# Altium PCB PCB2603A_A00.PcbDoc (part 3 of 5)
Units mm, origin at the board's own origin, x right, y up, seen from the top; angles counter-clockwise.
Board outline 35.56 x 55.88 mm, 8 copper layers (Top Layer, Signal Layer 1, Signal Layer 2, Signal Layer 3, Signal Layer 4, Signal Layer 5, Signal Layer 6, Bottom Layer), stack 1.497 mm thick; 167 components, 113 nets, 4957 pads, 645 vias.
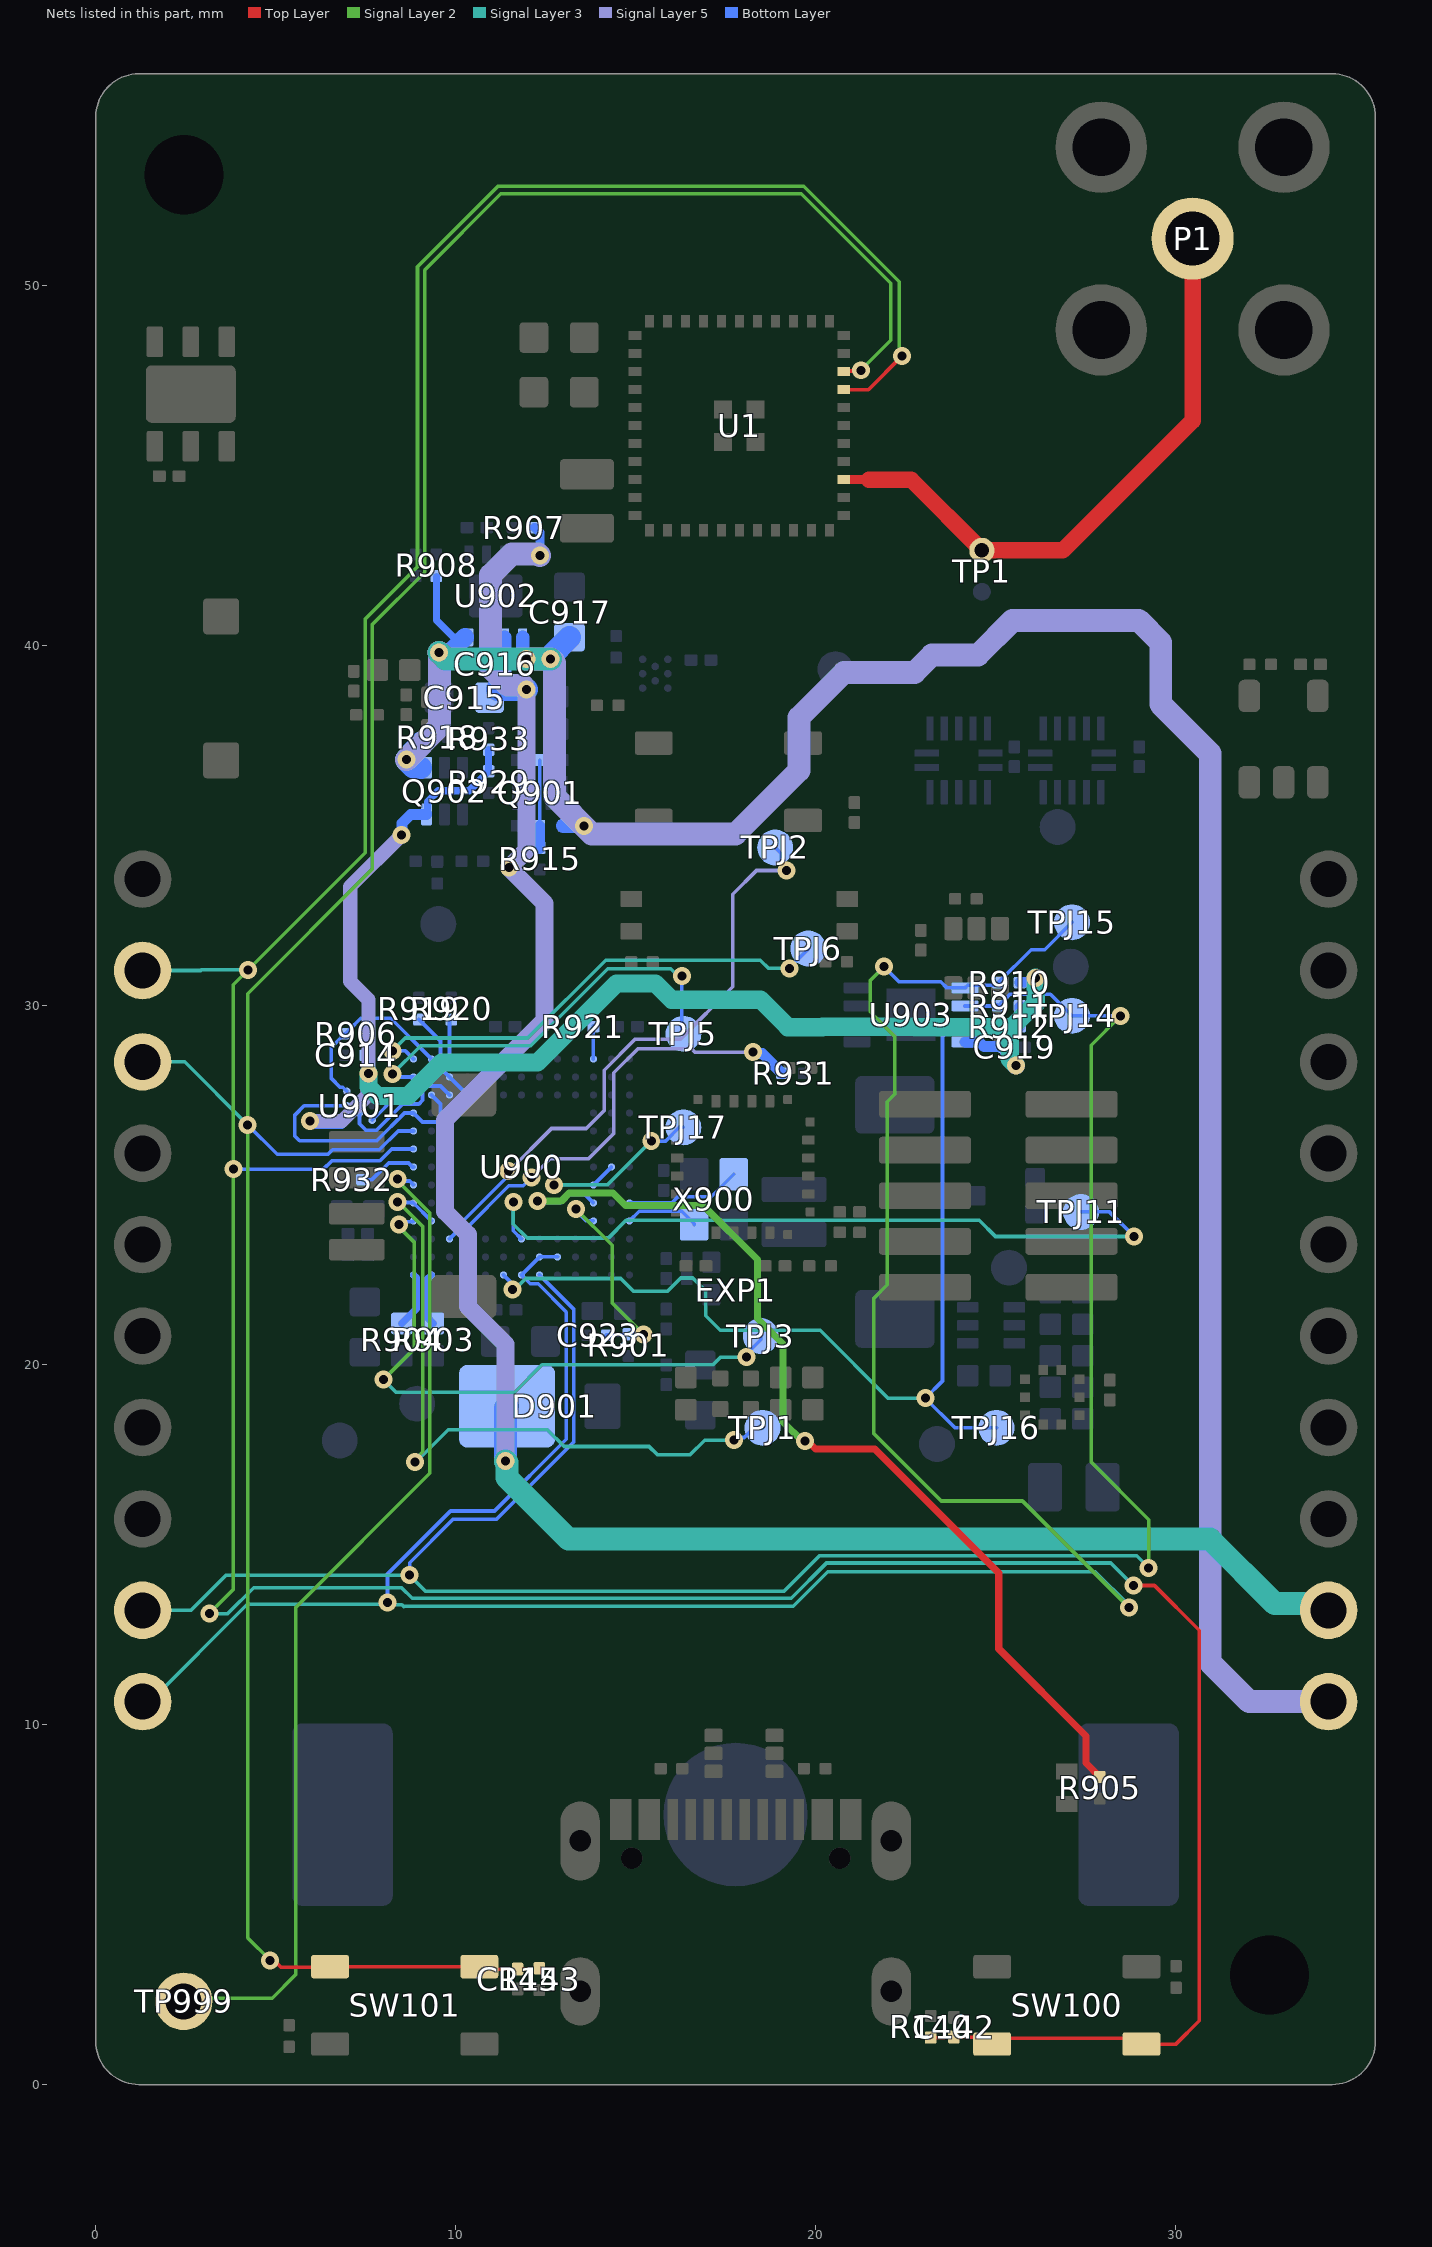
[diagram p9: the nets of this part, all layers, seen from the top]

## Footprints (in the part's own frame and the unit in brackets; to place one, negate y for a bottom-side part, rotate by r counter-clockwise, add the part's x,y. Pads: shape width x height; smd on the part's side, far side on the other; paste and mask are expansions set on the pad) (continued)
LOGO_SEGGER_8.0X4.0_SM [mil] "(210607)" (continued)
  round 0.8 on Mech2: 1(60.2,-56.26) 1(60.2,-56.26) 1(60.36,-56.74) 1(60.36,-56.74) 1(60.44,-56.9) 1(60.44,-56.9) 1(60.44,-56.82) 1(60.52,-29.06) 1(60.52,-29.06) 1(60.6,-57.14) 1(60.6,-57.14) 1(60.68,-57.3) 1(60.68,-57.3) 1(61.16,-36.58) 1(61.16,-36.58) 1(61.16,-29.46) 1(61.32,-57.94) 1(61.32,-57.94) 1(61.48,-29.7) 1(61.48,-29.7) 1(61.56,-58.02) 1(61.56,-58.02) 1(61.72,-58.1) 1(61.72,-58.1) 1(61.8,-36.42) 1(61.8,-36.42) 1(62.2,-58.26) 1(62.2,-58.26) 1(62.28,-40.98) 1(62.28,-40.98) 1(62.28,-36.1) 1(62.28,-36.1) 1(62.28,-30.5) 1(62.28,-30.5) 1(62.44,-58.26) 1(62.44,-58.26) 1(62.6,-35.94) 1(62.6,-35.94) 1(62.68,-58.34) 1(62.68,-58.34) 1(62.68,-35.86) 1(62.68,-30.82) 1(62.68,-30.82) 1(62.84,-41.06) 1(62.84,-41.06) 1(62.84,-31.06) 1(62.92,-58.34) 1(62.92,-58.34) 1(63.08,-35.46) 1(63.08,-35.46) 1(63.24,-58.26) 1(63.24,-58.26) 1(63.4,-34.98) 1(63.4,-34.98) 1(63.4,-32.02) 1(63.4,-32.02) 1(63.48,-34.74) 1(63.48,-34.74) 1(63.56,-58.26) 1(63.56,-58.26) 1(63.56,-32.34) 1(63.56,-32.34) 1(63.64,-41.22) 1(63.64,-41.22) 1(63.64,-34.42) 1(63.64,-34.42) 1(63.72,-34.26) 1(63.72,-34.18) 1(63.72,-34.18) 1(63.72,-32.74) 1(63.72,-32.74) 1(63.72,-32.66) 1(63.88,-58.18) 1(63.88,-58.18) 1(64.04,-41.38) 1(64.04,-41.38) 1(64.12,-58.18) 1(64.12,-58.18) 1(64.28,-41.46) 1(64.28,-41.46) 1(64.36,-58.02) 1(64.36,-58.02) 1(64.52,-57.94) 1(64.52,-57.94) 1(64.6,-41.62) 1(64.6,-41.62) 1(64.76,-57.78) 1(64.76,-57.78) 1(65,-42.02) 1(65,-42.02) 1(65.08,-57.46) 1(65.08,-57.46) 1(65.16,-57.3) 1(65.16,-57.3) 1(65.24,-42.34) 1(65.32,-57.06) 1(65.32,-57.06) 1(65.32,-42.5) 1(65.32,-42.5) 1(65.4,-56.82) 1(65.4,-56.74) 1(65.4,-56.74) 1(65.48,-56.5) 1(65.48,-56.5) 1(65.48,-56.18) 1(65.48,-56.18) 1(65.56,-55.94) 1(65.56,-55.94) 1(65.56,-55.14) 1(65.56,-53.54) 1(65.56,-51.94) 1(65.56,-50.34) 1(65.56,-48.74) 1(65.56,-47.14) 1(65.56,-45.54) 1(65.56,-43.94) 1(65.56,-43.46) 1(65.56,-43.46) 1(72.68,-54.02) 1(72.68,-54.02) 1(72.68,-52.66) 1(72.68,-51.06) 1(72.68,-49.46) 1(72.68,-47.86) 1(72.68,-46.26) 1(72.68,-44.66) 1(72.68,-43.06) 1(72.68,-41.46) 1(72.68,-39.86) 1(72.68,-38.18) 1(72.68,-36.58) 1(72.68,-34.98) 1(72.68,-33.38) 1(72.68,-31.78) 1(72.68,-30.5) 1(72.68,-30.5) 1(72.76,-54.58) 1(72.76,-54.58) 1(72.76,-54.26) 1(72.76,-30.18) 1(72.76,-29.94) 1(72.76,-29.94) 1(72.92,-55.3) 1(72.92,-55.3) 1(72.92,-55.06) 1(72.92,-55.06) 1(72.92,-29.38) 1(72.92,-29.38) 1(72.92,-29.14) 1(72.92,-29.14) 1(73,-55.54) 1(73,-55.54) 1(73,-28.98) 1(73,-28.98) 1(73.16,-55.78) 1(73.16,-55.78) 1(73.16,-28.74) 1(73.16,-28.74) 1(73.24,-55.94) 1(73.24,-28.58) 1(73.4,-56.26) 1(73.4,-56.26) 1(73.4,-28.26) 1(73.4,-28.26) 1(73.56,-56.42) 1(73.56,-56.42) 1(73.56,-28.1) 1(73.56,-28.1) 1(73.64,-56.58) 1(73.64,-56.58) 1(73.64,-27.94) 1(73.64,-27.94) 1(73.72,-56.66) 1(73.72,-56.66) 1(73.88,-56.74) 1(73.88,-56.74) 1(73.88,-27.7) 1(73.88,-27.7) 1(74.04,-56.9) 1(74.04,-56.9) 1(74.04,-27.62) 1(74.04,-27.62) 1(74.2,-27.46) 1(74.2,-27.46) 1(74.36,-57.06) 1(74.36,-57.06) 1(74.36,-27.46) 1(74.36,-27.46) 1(74.6,-57.14) 1(74.6,-57.14) 1(74.6,-27.3) 1(74.6,-27.3) 1(74.76,-57.22) 1(74.76,-57.22) 1(74.76,-27.22) 1(74.76,-27.22) 1(75,-57.3) 1(75,-57.3) 1(75,-27.22) 1(75,-27.22) 1(75.48,-27.06) 1(75.48,-27.06) 1(75.96,-57.46) 1(75.96,-57.46) 1(75.96,-26.98) 1(75.96,-26.98) 1(75.96,-26.98) 1(76.52,-57.54) 1(76.52,-57.54) 1(76.52,-26.98) 1(76.52,-26.98) 1(77.16,-26.9) 1(77.16,-26.9) 1(79.96,-51.94) 1(79.96,-51.94) 1(79.96,-51.06) 1(79.96,-49.46) 1(79.96,-47.86) 1(79.96,-46.26) 1(79.96,-44.66) 1(79.96,-44.02) 1(79.96,-44.02) 1(79.96,-38.74) 1(79.96,-38.74) 1(79.96,-38.18) 1(79.96,-36.58) 1(79.96,-34.98) 1(79.96,-33.38) 1(79.96,-32.26) 1(79.96,-32.26) 1(93.72,-38.74) 1(93.72,-38.74) 1(94.2,-44.02) 1(94.2,-44.02) 1(94.2,-38.82) 1(94.2,-38.82) 1(94.68,-43.94) 1(94.68,-43.94) 1(94.68,-38.82) 1(94.68,-38.82) 1(95.08,-43.94) 1(95.08,-43.94) 1(95.08,-38.9) 1(95.08,-38.9) 1(95.24,-26.9) 1(95.24,-26.9) 1(95.48,-43.86) 1(95.48,-43.86) 1(95.48,-38.9) 1(95.48,-38.9) 1(95.72,-32.26) 1(95.72,-32.26) 1(95.72,-26.98) 1(95.72,-26.98) 1(95.8,-43.78) 1(95.8,-43.78) 1(95.8,-39.06) 1(95.8,-39.06) 1(96.12,-43.62) 1(96.12,-43.62) 1(96.12,-39.14) 1(96.12,-39.14) 1(96.2,-32.18) 1(96.2,-32.18) 1(96.2,-26.98) 1(96.2,-26.98) 1(96.28,-26.98) 1(96.44,-43.54) 1(96.44,-43.54) 1(96.44,-39.3) 1(96.44,-39.3) 1(96.6,-32.18) 1(96.6,-32.18) 1(96.68,-51.94) 1(96.68,-51.94) 1(96.92,-43.22) 1(96.92,-43.22) 1(97.08,-43.06) 1(97.08,-42.98) 1(97.08,-42.98) 1(97.16,-57.54) 1(97.16,-57.54) 1(97.16,-52.02) 1(97.16,-52.02) 1(97.16,-39.78) 1(97.16,-39.78) 1(97.24,-39.86) 1(97.4,-32.02) 1(97.4,-32.02) 1(97.4,-27.22) 1(97.4,-27.22) 1(97.48,-42.58) 1(97.48,-42.58) 1(97.48,-40.26) 1(97.48,-40.26) 1(97.56,-52.02) 1(97.56,-52.02) 1(97.56,-42.26) 1(97.56,-42.26) 1(97.56,-40.5) 1(97.56,-40.5) 1(97.64,-42.02) 1(97.64,-42.02) 1(97.72,-41.7) 1(97.72,-41.7) 1(97.72,-41.46) 1(97.72,-41.14) 1(97.72,-41.14) 1(97.72,-31.86) 1(97.72,-31.86) 1(97.72,-27.3) 1(97.72,-27.3) 1(97.96,-31.78) 1(98.04,-31.78) 1(98.04,-31.78) 1(98.04,-27.46) 1(98.04,-27.46) 1(98.28,-31.62) 1(98.28,-31.62) 1(98.36,-57.3) 1(98.36,-57.3) 1(98.36,-52.18) 1(98.36,-52.18) 1(98.52,-31.38) 1(98.52,-31.38) 1(98.52,-27.78) 1(98.52,-27.78) 1(98.68,-57.14) 1(98.68,-57.14) 1(98.76,-31.22) 1(98.76,-31.22) 1(98.76,-28.02) 1(98.76,-28.02) 1(98.92,-56.98) 1(98.92,-56.98) 1(98.92,-30.98) 1(98.92,-30.98) 1(98.92,-28.26) 1(98.92,-28.26) 1(99,-52.5) 1(99,-52.5) 1(99,-30.74) 1(99,-30.74) 1(99,-28.5) 1(99,-28.5) 1(99.08,-28.58) 1(99.16,-30.5) 1(99.16,-30.5) 1(99.16,-28.74) 1(99.16,-28.74) 1(99.24,-56.82) 1(99.24,-56.82) 1(99.24,-30.26) 1(99.24,-30.26) 1(99.24,-28.98) 1(99.24,-28.98) 1(99.32,-52.66) 1(99.32,-30.18) 1(99.32,-29.94) 1(99.32,-29.94) 1(99.32,-29.3) 1(99.32,-29.3) 1(99.48,-56.66) 1(99.48,-56.66) 1(99.48,-52.82) 1(99.48,-52.82) 1(99.64,-56.42) 1(99.64,-56.42) 1(99.72,-53.06) 1(99.72,-53.06) 1(99.88,-56.18) 1(99.88,-56.18) 1(99.88,-53.3) 1(99.88,-53.3) 1(99.96,-55.94) 1(99.96,-55.94) 1(99.96,-55.94) 1(100.12,-55.7) 1(100.12,-55.7) 1(100.12,-53.78) 1(100.12,-53.78) 1(100.2,-55.38) 1(100.2,-55.38) 1(100.2,-55.06) 1(100.2,-55.06) 1(100.2,-54.42) 1(100.2,-54.42) 1(100.2,-54.26) 1(100.2,-54.1) 1(100.2,-54.1) 1(100.28,-54.74) 1(100.28,-54.74) 1(105.4,-54.98) 1(105.4,-54.98) 1(105.4,-54.66) 1(105.4,-53.06) 1(105.4,-51.46) 1(105.4,-49.86) 1(105.4,-48.26) 1(105.4,-46.66) 1(105.4,-45.06) 1(105.4,-43.46) 1(105.4,-41.86) 1(105.4,-40.26) 1(105.4,-38.58) 1(105.4,-36.98) 1(105.4,-35.38) 1(105.4,-33.78) 1(105.4,-32.18) 1(105.4,-31.06) 1(105.4,-31.06) 1(105.48,-55.38) 1(105.48,-55.38) 1(105.48,-30.58) 1(105.64,-56.02) 1(105.64,-56.02) 1(105.64,-29.38) 1(105.64,-29.38) 1(105.72,-29.14) 1(105.72,-29.14) 1(105.8,-56.34) 1(105.8,-56.34) 1(105.8,-56.34) 1(105.8,-28.98) 1(105.8,-28.98) 1(105.8,-28.98) 1(105.88,-28.74) 1(105.88,-28.74) 1(106.04,-28.42) 1(106.04,-28.42) 1(106.12,-56.82) 1(106.12,-56.82) 1(106.2,-28.26) 1(106.2,-28.26) 1(106.36,-27.94) 1(106.36,-27.94) 1(106.52,-27.86) 1(106.52,-27.86) 1(106.6,-57.3) 1(106.6,-57.3) 1(106.68,-27.7) 1(106.68,-27.7) 1(106.84,-57.46) 1(106.84,-57.46) 1(106.84,-27.62) 1(106.84,-27.62) 1(107,-27.46) 1(107,-27.46) 1(107.16,-57.62) 1(107.16,-57.62) 1(107.16,-27.46) 1(107.16,-27.46) 1(107.24,-27.38) 1(107.32,-27.3) 1(107.32,-27.3) 1(107.48,-57.7) 1(107.48,-57.7) 1(107.56,-27.22) 1(107.56,-27.22) 1(107.8,-27.22) 1(107.8,-27.22) 1(108.2,-27.06) 1(108.2,-27.06) 1(108.68,-57.94) 1(108.68,-57.94) 1(108.76,-26.98) 1(108.76,-26.98) 1(109.32,-26.98) 1(109.32,-26.98) 1(109.56,-57.94) 1(109.56,-57.94) 1(109.96,-26.9) 1(109.96,-26.9) 1(110.04,-57.86) 1(110.04,-57.86) 1(110.44,-57.78) 1(110.44,-57.78) 1(111.08,-57.62) 1(111.08,-57.62) 1(111.4,-57.46) 1(111.4,-57.46) 1(111.64,-57.3) 1(111.64,-57.3) 1(111.96,-57.06) 1(111.96,-57.06) 1(112.12,-56.9) 1(112.12,-56.9) 1(112.36,-56.58) 1(112.36,-56.58) 1(112.44,-56.34) 1(112.44,-56.34) 1(112.44,-56.34) 1(112.6,-56.02) 1(112.6,-56.02) 1(112.76,-55.38) 1(112.76,-55.38) 1(112.84,-54.98) 1(112.84,-54.98) 1(112.84,-54.66) 1(112.84,-53.06) 1(112.84,-51.46) 1(112.84,-49.86) 1(112.84,-48.26) 1(112.84,-46.66) 1(112.84,-45.62) 1(112.84,-45.62) 1(112.84,-40.34) 1(112.84,-40.34) 1(112.84,-40.26) 1(112.84,-38.58) 1(112.84,-36.98) 1(112.84,-35.38) 1(112.84,-33.78) 1(112.84,-32.18) 1(112.84,-32.18) 1(112.84,-32.18) 1(120.68,-45.62) 1(120.68,-45.62) 1(121.4,-45.7) 1(121.4,-45.7) 1(121.88,-32.18) 1(121.88,-32.18) 1(122.04,-45.7) 1(122.04,-45.7) 1(122.2,-32.18) 1(122.28,-40.34) 1(122.28,-40.34) 1(122.52,-32.26) 1(122.52,-32.26) 1(122.92,-40.26) 1(122.92,-40.26) 1(122.92,-26.9) 1(122.92,-26.9) 1(123,-40.26) 1(123.16,-45.86) 1(123.16,-45.86) 1(123.16,-32.26) 1(123.16,-32.26) 1(123.56,-45.94) 1(123.56,-45.94) 1(123.64,-32.34) 1(123.64,-32.34) 1(123.64,-26.98) 1(123.64,-26.98) 1(124.04,-46.1) 1(124.04,-46.1) 1(124.04,-40.1) 1(124.04,-40.1) 1(124.2,-46.18) 1(124.2,-46.18) 1(124.2,-32.5) 1(124.2,-32.5) 1(124.36,-46.34) 1(124.36,-46.34) 1(124.36,-26.98) 1(124.36,-26.98) 1(124.6,-32.58) 1(124.6,-32.58) 1(124.68,-46.5) 1(124.68,-46.5) 1(124.92,-46.66) 1(125,-39.78) 1(125,-39.78) 1(125,-32.82) 1(125,-32.82) 1(125,-27.06) 1(125,-27.06) 1(125.08,-46.9) 1(125.08,-46.9) 1(125.16,-47.14) 1(125.16,-47.14) 1(125.16,-39.7) 1(125.16,-39.7) 1(125.24,-32.9) 1(125.24,-32.9) 1(125.32,-47.3) 1(125.32,-47.3) 1(125.4,-39.54) 1(125.4,-39.54) 1(125.4,-32.98) 1(125.4,-32.98) 1(125.48,-47.78) 1(125.48,-47.78) 1(125.56,-48.1) 1(125.56,-48.1) 1(125.64,-48.26) 1(125.64,-33.14) 1(125.64,-33.14) 1(125.64,-27.06) 1(125.64,-27.06) 1(125.72,-48.66) 1(125.72,-48.66) 1(125.72,-39.38) 1(125.72,-39.38) 1(125.8,-33.22) 1(125.8,-33.22) 1(125.88,-49.38) 1(125.88,-49.38) 1(125.96,-33.38) 1(125.96,-33.38) 1(126.04,-51.06) 1(126.04,-51.06) 1(126.04,-50.18) 1(126.04,-50.18) 1(126.04,-49.86) 1(126.04,-33.54) 1(126.04,-33.54) 1(126.12,-51.46) 1(126.2,-52.18) 1(126.2,-52.18) 1(126.2,-33.62) 1(126.2,-33.62) 1(126.28,-53.14) 1(126.28,-53.14) 1(126.28,-53.06) 1(126.36,-33.78) 1(126.36,-33.78) 1(126.44,-54.02) 1(126.44,-54.02) 1(126.44,-38.66) 1(126.44,-38.66) 1(126.44,-38.58) 1(126.44,-34.02) 1(126.44,-34.02) 1(126.44,-33.78) 1(126.6,-54.82) 1(126.6,-54.82) 1(126.6,-54.66) 1(126.6,-38.42) 1(126.6,-38.42) 1(126.6,-34.18) 1(126.6,-34.18) 1(126.76,-34.5) 1(126.76,-34.5) 1(126.84,-55.78) 1(126.84,-55.78) 1(126.84,-37.94) 1(126.84,-37.94) 1(126.84,-34.74) 1(126.84,-34.74) 1(126.92,-37.7) 1(126.92,-37.7) 1(126.92,-37.46) 1(126.92,-37.46) 1(126.92,-34.9) 1(126.92,-34.9) 1(126.92,-27.22) 1(126.92,-27.22) 1(127,-56.02) 1(127,-56.02) 1(127,-37.22) 1(127,-37.22) 1(127,-35.3) 1(127,-35.3) 1(127,-35.14) 1(127,-35.14) 1(127.08,-56.26) 1(127.08,-56.26) 1(127.08,-36.98) 1(127.08,-36.74) 1(127.08,-36.74) 1(127.08,-35.78) 1(127.08,-35.78) 1(127.08,-35.38) 1(127.16,-56.34) 1(127.24,-56.5) 1(127.24,-56.5) 1(127.32,-56.66) 1(127.32,-56.66) 1(127.48,-56.82) 1(127.48,-56.82) 1(127.48,-27.38) 1(127.48,-27.38) 1(127.56,-56.98) 1(127.56,-56.98) 1(127.56,-27.38) 1(127.72,-57.06) 1(127.72,-57.06) 1(127.88,-57.22) 1(127.88,-57.22) 1(128.04,-57.3) 1(128.04,-57.3) 1(128.04,-27.46) 1(128.04,-27.46) 1(128.2,-57.46) 1(128.2,-57.46) 1(128.36,-57.54) 1(128.36,-57.54) 1(128.6,-57.62) 1(128.6,-57.62) 1(128.6,-27.62) 1(128.6,-27.62) 1(128.76,-57.7) 1(128.76,-57.7) 1(129.16,-42.82) 1(129.16,-42.82) 1(129.56,-27.94) 1(129.56,-27.94) 1(129.64,-43.06) 1(129.64,-43.06) 1(130.04,-28.18) 1(130.04,-28.18) 1(130.12,-43.22) 1(130.12,-43.22) 1(130.12,-42.58) 1(130.12,-42.58) 1(130.2,-57.94) 1(130.2,-57.94) 1(130.36,-42.42) 1(130.36,-42.42) 1(130.52,-43.38) 1(130.52,-43.38) 1(130.52,-28.34) 1(130.52,-28.34) 1(130.68,-43.46) 1(130.68,-42.34) 1(130.68,-42.34) 1(131.32,-43.86) 1(131.32,-43.86) 1(131.32,-28.82) 1(131.32,-28.82) 1(131.4,-41.86) 1(131.4,-41.86) 1(131.4,-41.86) 1(131.56,-57.94) 1(131.56,-57.94) 1(131.56,-28.98) 1(131.64,-44.1) 1(131.64,-44.1) 1(131.64,-29.06) 1(131.64,-29.06) 1(131.72,-41.7) 1(131.72,-41.7) 1(131.96,-57.86) 1(131.96,-57.86) 1(131.96,-41.54) 1(131.96,-41.54) 1(132.04,-29.38) 1(132.04,-29.38) 1(132.28,-57.78) 1(132.28,-57.78) 1(132.36,-41.14) 1(132.36,-41.14) 1(132.36,-29.62) 1(132.36,-29.62) 1(132.52,-44.98) 1(132.52,-44.98) 1(132.6,-57.62) 1(132.6,-57.62) 1(132.6,-45.06) 1(132.6,-40.98) 1(132.6,-40.98) 1(132.6,-29.94) 1(132.6,-29.94) 1(132.68,-45.38) 1(132.68,-45.38) 1(132.92,-57.54) 1(132.92,-57.54) 1(132.92,-45.7) 1(132.92,-45.7) 1(132.92,-40.5) 1(132.92,-40.5) 1(132.92,-30.34) 1(132.92,-30.34) 1(133.08,-46.1) 1(133.08,-46.1) 1(133.16,-57.38) 1(133.16,-57.38) 1(133.16,-40.34) 1(133.16,-40.34) 1(133.16,-30.58) 1(133.24,-46.58) 1(133.24,-46.58) 1(133.24,-40.26) 1(133.32,-46.66) 1(133.32,-40.1) 1(133.32,-40.1) 1(133.4,-30.98) 1(133.4,-30.98) 1(133.48,-57.22) 1(133.48,-57.22) 1(133.48,-39.78) 1(133.48,-39.78) 1(133.56,-48.26) 1(133.64,-50.82) 1(133.64,-50.82) 1(133.64,-49.86) 1(133.64,-48.98) 1(133.64,-48.98) 1(133.64,-39.54) 1(133.64,-39.54) 1(133.64,-31.38) 1(133.64,-31.38) 1(133.72,-56.98) 1(133.72,-56.98) 1(133.72,-51.38) 1(133.72,-51.38) 1(133.72,-39.3) 1(133.72,-39.3) 1(133.8,-52.1) 1(133.8,-52.1) 1(133.8,-51.78) 1(133.8,-51.78) 1(133.8,-51.46) 1(133.88,-56.74) 1(133.88,-56.74) 1(133.88,-39.06) 1(133.88,-39.06) 1(133.96,-52.74) 1(133.96,-52.74) 1(133.96,-38.74) 1(133.96,-38.74) 1(133.96,-32.18) 1(133.96,-32.18) 1(133.96,-32.18) 1(134.04,-56.58) 1(134.04,-56.58) 1(134.04,-53.22) 1(134.04,-53.22) 1(134.04,-53.06) 1(134.04,-38.58) 1(134.04,-38.5) 1(134.04,-38.5) 1(134.12,-32.66) 1(134.12,-32.66) 1(134.2,-56.34) 1(134.2,-56.26) 1(134.2,-56.26) 1(134.2,-53.7) 1(134.2,-53.7) 1(134.2,-38.18) 1(134.2,-38.18) 1(134.2,-37.94) 1(134.2,-37.94) 1(134.2,-33.06) 1(134.2,-33.06) 1(134.28,-54.18) 1(134.28,-54.18) 1(134.36,-56.02) 1(134.36,-56.02) 1(134.36,-33.54) 1(134.36,-33.54) 1(134.44,-55.78) 1(134.44,-55.78) 1(134.44,-54.66) 1(134.44,-54.58) 1(134.44,-54.58) 1(134.44,-36.98) 1(134.44,-36.98) 1(134.44,-36.98) 1(134.44,-34.58) 1(134.44,-34.58) 1(134.44,-34.02) 1(134.44,-34.02) 1(134.44,-33.78) 1(134.52,-36.34) 1(134.52,-36.34) 1(134.52,-35.38) 1(134.52,-35.06) 1(134.52,-35.06) 1(135.4,-5.14) 1(135.4,-5.14) 1(135.4,14.54) 1(135.4,14.54) 1(135.8,-14.34) 1(135.8,-14.34) 1(135.8,-5.22) 1(135.8,-5.22) 1(135.8,5.34) 1(135.8,5.34) 1(135.8,14.46) 1(135.8,14.46) 1(136.2,-5.22) 1(136.2,-5.22) 1(136.2,14.46) 1(136.2,14.46) 1(137,-14.1) 1(137,-14.1) 1(137,-5.38) 1(137,-5.38) 1(137,5.58) 1(137,5.58) 1(137,14.3) 1(137,14.3) 1(137.16,-14.02) 1(137.64,-13.78) 1(137.64,-13.78) 1(137.64,-5.7) 1(137.64,-5.7) 1(137.64,13.98) 1(137.64,13.98) 1(137.8,-13.62) 1(137.8,-13.62) 1(137.8,-5.86) 1(137.8,-5.86) 1(137.8,5.98) 1(137.8,5.98) 1(137.96,-13.54) 1(137.96,-13.54) 1(137.96,-5.94) 1(137.96,-5.94) 1(137.96,13.66) 1(137.96,13.66) 1(138.04,-5.94) 1(138.12,13.58) 1(138.12,13.58) 1(138.28,-13.22) 1(138.28,-13.22) 1(138.28,-6.26) 1(138.28,-6.26) 1(138.28,6.46) 1(138.28,6.46) 1(138.28,13.42) 1(138.28,13.42) 1(138.36,-13.06) 1(138.36,-13.06) 1(138.36,-6.42) 1(138.36,-6.42) 1(138.36,6.62) 1(138.36,6.62) 1(138.36,13.18) 1(138.36,13.18) 1(138.36,13.42) 1(138.52,-12.82) 1(138.52,-12.82) 1(138.52,-6.66) 1(138.52,-6.66) 1(138.52,6.78) 1(138.52,6.78) 1(138.52,13.02) 1(138.52,13.02) 1(138.6,-12.66) 1(138.6,-12.66) 1(138.6,6.94) 1(138.68,-12.42) 1(138.76,-12.18) 1(138.76,-12.18) 1(138.76,-7.38) 1(138.76,-7.38) 1(138.76,7.5) 1(138.76,7.5) 1(138.76,12.3) 1(138.76,12.3) 1(138.92,-11.86) 1(138.92,-11.86) 1(138.92,-11.62) 1(138.92,-11.62) 1(138.92,-7.94) 1(138.92,-7.94) 1(138.92,-7.62) 1(138.92,-7.62) 1(138.92,-7.62) 1(138.92,7.82) 1(138.92,7.82) 1(138.92,8.06) 1(138.92,8.06) 1(138.92,11.74) 1(138.92,11.74) 1(138.92,11.82) 1(138.92,12.06) 1(138.92,12.06) 1(139,-11.3) 1(139,-11.3) 1(139,8.38) 1(139,8.38) 1(139.08,-10.9) 1(139.08,-10.9) 1(139.08,-10.82) 1(139.08,-9.22) 1(139.08,-8.58) 1(139.08,-8.58) 1(139.08,8.62) 1(139.08,8.78) 1(139.08,8.78) 1(139.08,10.22) 1(139.08,11.1) 1(139.08,11.1) 1(145,78.78) 1(145,78.78) 1(145.32,72.22) 1(145.32,72.22) 1(145.56,-72.02) 1(145.56,-72.02) 1(145.56,72.14) 1(145.56,72.14) 1(145.64,-78.58) 1(145.64,-78.58) 1(145.64,78.7) 1(145.64,78.7) 1(145.88,-71.94) 1(145.88,-71.94) 1(145.88,72.14) 1(145.88,72.14) 1(146.12,-71.94) 1(146.12,-71.94) 1(146.12,72.06) 1(146.12,72.06) 1(146.28,78.7) 1(146.28,78.7) 1(146.44,-71.86) 1(146.44,-71.86) 1(146.44,71.98) 1(146.44,71.98) 1(146.68,-71.78) 1(146.68,-71.78) 1(146.68,71.9) 1(146.68,71.9) 1(146.92,78.62) 1(146.92,78.62) 1(147,-71.62) 1(147,-71.62) 1(147,71.82) 1(147,71.82) 1(147.24,-71.54) 1(147.24,-71.54) 1(147.24,71.74) 1(147.24,71.74) 1(147.48,-71.38) 1(147.48,-71.38) 1(147.56,-78.34) 1(147.56,-78.34) 1(147.56,78.46) 1(147.56,78.46) 1(147.72,-71.3) 1(147.72,-71.3) 1(147.72,71.42) 1(147.72,71.42) 1(147.96,71.34) 1(147.96,71.34) 1(148.12,-78.18) 1(148.12,-78.18) 1(148.12,78.3) 1(148.12,78.3) 1(148.2,71.18) 1(148.2,71.18) 1(148.44,-70.82) 1(148.44,-70.82) 1(148.44,70.94) 1(148.44,70.94) 1(148.44,71.02) 1(148.68,70.78) 1(148.68,70.78) 1(148.76,-78.02) 1(148.76,-78.02) 1(148.76,-70.5) 1(148.76,78.14) 1(148.76,78.14) 1(149.32,-69.94) 1(149.32,-69.94) 1(149.32,70.14) 1(149.32,70.14) 1(149.32,77.98) 1(149.32,77.98) 1(149.48,-69.7) 1(149.48,-69.7) 1(149.48,69.9) 1(149.48,69.9) 1(149.72,-69.46) 1(149.72,-69.46) 1(149.72,69.66) 1(149.72,69.66) 1(149.88,69.42) 1(149.88,69.42) 1(149.88,77.74) 1(149.88,77.74) 1(149.96,69.42) 1(150.04,-68.98) 1(150.04,-68.98) 1(150.04,69.1) 1(150.04,69.1) 1(150.12,-68.9) 1(150.2,-68.66) 1(150.2,-68.66) 1(150.2,68.86) 1(150.2,68.86) 1(150.28,-68.42) 1(150.28,-68.42) 1(150.28,68.54) 1(150.28,68.54) 1(150.44,-77.3) 1(150.44,-77.3) 1(150.44,-68.1) 1(150.44,-68.1) 1(150.44,68.3) 1(150.44,68.3) 1(150.44,77.42) 1(150.44,77.42) 1(150.52,77.42) 1(150.6,-67.46) 1(150.6,-67.46) 1(150.6,67.74) 1(150.68,-67.3) 1(150.68,-67.22) 1(150.68,-67.22) 1(150.76,-66.82) 1(150.76,-66.82) 1(150.84,-66.5) 1(150.84,-66.5) 1(150.84,-66.18) 1(150.84,-66.18) 1(150.84,66.38) 1(150.84,66.38) 1(150.84,66.7) 1(150.84,66.7) 1(150.92,-65.86) 1(150.92,-65.86) 1(150.92,-65.7) 1(150.92,-64.1) 1(150.92,-62.5) 1(150.92,-60.9) 1(150.92,-59.22) 1(150.92,-57.62) 1(150.92,-56.02) 1(150.92,-54.42) 1(150.92,-52.82) 1(150.92,-51.22) 1(150.92,-49.62) 1(150.92,-48.02) 1(150.92,-46.42) 1(150.92,-44.82) 1(150.92,-43.14) 1(150.92,-41.54) 1(150.92,-39.94) 1(150.92,-38.34) 1(150.92,-36.74) 1(150.92,-35.14) 1(150.92,-33.54) 1(150.92,-31.94) 1(150.92,-30.34) 1(150.92,-28.74) 1(150.92,-27.06) 1(150.92,-25.46) 1(150.92,-23.86) 1(150.92,-22.26) 1(150.92,-20.66) 1(150.92,-19.06) 1(150.92,-17.46) 1(150.92,-15.86) 1(150.92,-14.26) 1(150.92,-12.66) 1(150.92,-10.98) 1(150.92,-9.38) 1(150.92,-7.78) 1(150.92,-6.18) 1(150.92,-4.58) 1(150.92,-2.98) 1(150.92,-1.38) 1(150.92,0.22) 1(150.92,1.82) 1(150.92,3.42) 1(150.92,5.1) 1(150.92,6.7) 1(150.92,8.3) 1(150.92,9.9) 1(150.92,11.5) 1(150.92,13.1) 1(150.92,14.7) 1(150.92,16.3) 1(150.92,17.9) 1(150.92,19.5) 1(150.92,21.18) 1(150.92,22.78) 1(150.92,24.38) 1(150.92,25.98) 1(150.92,27.58) 1(150.92,29.18) 1(150.92,30.78) 1(150.92,32.38) 1(150.92,33.98) 1(150.92,35.58) 1(150.92,37.26) 1(150.92,38.86) 1(150.92,40.46) 1(150.92,42.06) 1(150.92,43.66) 1(150.92,45.26) 1(150.92,46.86) 1(150.92,48.46) 1(150.92,50.06) 1(150.92,51.66) 1(150.92,53.34) 1(150.92,54.94) 1(150.92,56.54) 1(150.92,58.14) 1(150.92,59.74) 1(150.92,61.34) 1(150.92,62.94) 1(150.92,64.54) 1(150.92,66.06) 1(150.92,66.06) 1(150.92,66.14) 1(151,-76.98) 1(151,-76.98) 1(151,77.18) 1(151,77.18) 1(151.08,-76.98) 1(151.48,-76.66) 1(151.48,-76.66) 1(151.48,76.86) 1(151.48,76.86) 1(152.04,-76.34) 1(152.04,-76.34) 1(152.04,76.46) 1(152.04,76.46) 1(152.52,76.06) 1(152.52,76.06) 1(152.92,75.82) 1(153,75.74) 1(153,75.74) 1(153.24,-75.3) 1(153.48,-75.14) 1(153.48,-75.14) 1(153.88,74.86) 1(153.88,74.86) 1(154.28,-74.18) 1(154.28,-74.18) 1(154.44,74.22) 1(154.68,-73.78) 1(154.68,-73.78) 1(154.68,73.9) 1(154.68,73.9) 1(154.76,-73.7) 1(155,-73.22) 1(155,-73.22) 1(155.32,-72.74) 1(155.32,-72.74) 1(155.32,72.94) 1(155.32,72.94) 1(155.64,72.62) 1(155.72,-72.18) 1(155.72,-72.18) 1(155.72,72.38) 1(155.72,72.38) 1(155.8,-72.1) 1(155.96,-71.7) 1(155.96,-71.7) 1(155.96,71.82) 1(155.96,71.82) 1(156.28,-71.14) 1(156.28,-71.14) 1(156.28,71.26) 1(156.28,71.26) 1(156.44,71.02) 1(156.52,-70.5) 1(156.52,-70.5) 1(156.52,-70.5) 1(156.76,-69.94) 1(156.76,-69.94) 1(156.76,70.14) 1(156.76,70.14) 1(156.92,-69.38) 1(156.92,-69.38) 1(156.92,69.5) 1(156.92,69.5) 1(157,69.42) 1(157.08,-68.9) 1(157.08,68.94) 1(157.08,68.94) 1(157.24,-68.1) 1(157.24,-68.1) 1(157.24,68.3) 1(157.24,68.3) 1(157.32,67.74) 1(157.4,-67.3) 1(157.4,-66.82) 1(157.4,-66.82) 1(157.4,-66.18) 1(157.4,-66.18) 1(157.4,66.38) 1(157.4,66.38) 1(157.4,67.02) 1(157.4,67.02) 1(157.48,-65.7) 1(157.48,-65.54) 1(157.48,-65.54) 1(157.48,-64.1) 1(157.48,-62.5) 1(157.48,-60.9) 1(157.48,-59.22) 1(157.48,-57.62) 1(157.48,-56.02) 1(157.48,-54.42) 1(157.48,-52.82) 1(157.48,-51.22) 1(157.48,-49.62) 1(157.48,-48.02) 1(157.48,-46.42) 1(157.48,-44.82) 1(157.48,-43.14) 1(157.48,-41.54) 1(157.48,-39.94) 1(157.48,-38.34) 1(157.48,-36.74) 1(157.48,-35.14) 1(157.48,-33.54) 1(157.48,-31.94) 1(157.48,-30.34) 1(157.48,-28.74) 1(157.48,-27.06) 1(157.48,-25.46) 1(157.48,-23.86) 1(157.48,-22.26) 1(157.48,-20.66) 1(157.48,-19.06) 1(157.48,-17.46) 1(157.48,-15.86) 1(157.48,-14.26) 1(157.48,-12.66) 1(157.48,-10.98) 1(157.48,-9.38) 1(157.48,-7.78) 1(157.48,-6.18) 1(157.48,-4.58) 1(157.48,-2.98) 1(157.48,-1.38) 1(157.48,0.22) 1(157.48,1.82) 1(157.48,3.42) 1(157.48,5.1) 1(157.48,6.7) 1(157.48,8.3) 1(157.48,9.9) 1(157.48,11.5) 1(157.48,13.1) 1(157.48,14.7) 1(157.48,16.3) 1(157.48,17.9) 1(157.48,19.5) 1(157.48,21.18) 1(157.48,22.78) 1(157.48,24.38) 1(157.48,25.98) 1(157.48,27.58) 1(157.48,29.18) 1(157.48,30.78) 1(157.48,32.38) 1(157.48,33.98) 1(157.48,35.58) 1(157.48,37.26) 1(157.48,38.86) 1(157.48,40.46) 1(157.48,42.06) 1(157.48,43.66) 1(157.48,45.26) 1(157.48,46.86) 1(157.48,48.46) 1(157.48,50.06) 1(157.48,51.66) 1(157.48,53.34) 1(157.48,54.94) 1(157.48,56.54) 1(157.48,58.14) 1(157.48,59.74) 1(157.48,61.34) 1(157.48,62.94) 1(157.48,64.54) 1(157.48,65.66) 1(157.48,65.66) 1(157.48,66.14)
  round 0.79 on Mech2: 1(-15.75,0) 1(0,-15.75) 1(0,15.75) 1(15.75,0)
  silkscreen extent -157,-79 157,79
LOGO_SILABS_W14.0 [mm] "LOGO_SILABS_W14.0"
  silkscreen extent 0.03,0 13.99,6.83
POWERPAK_SC70-6_L [mm] "POWERPAK SC70-6 Hich Dencity (Class C) (Vishay)"
  rrect10% 0.325x0.3 smd paste-0.025 mask+0.07: 1(-0.913,0.65) 2(-0.913,0) 3(-0.913,-0.65) 4(0.913,-0.65) 5(0.913,0) 6(0.913,0.65)
  rrect10% 0.95x0.613 smd paste-0.025 mask+0.07: 7(0,0.466) 8(0,-0.466)
  silkscreen extent -1.03,-1.02 1.02,1.05, body extent -1.02,-1.02 1.02,1.05, height 0.8
PROTO_TH [mm] "Test Point, 1.0 mm (= TP_1.0_D62)"
  round 1.6 hole 1: 1(0,0)
  silkscreen extent -0.84,-0.84 0.84,0.84
QFN14_M040_2.0X2.0_TI_RUC [mm] "QFN 14 Leads, Pitch 0.4 mm, 2.0 x 2.0 H: 0.37, TI: RUC (170308)"
  rrect20% 0.68x0.2 smd paste+0 mask+0.05: 1(-0.885,0.8) 2(-0.885,0.4) 3(-0.885,0) 4(-0.885,-0.4) 5(-0.885,-0.8) 8(0.885,-0.8) 9(0.885,-0.4) 10(0.885,0) 11(0.885,0.4) 12(0.885,0.8)
  rrect20% 0.2x0.68 smd paste+0 mask+0.05: 6(-0.2,-0.885) 7(0.2,-0.885) 13(0.2,0.885) 14(-0.2,0.885)
  silkscreen extent -1,-1 1,1, body extent -1,-1 1,1, height 0.41
QFN24_M050_4.0X4.0_NO_EP_ICM-20689 [mm] "QFN24, Pitch 0.50 4.0x4.0 H0.8 (210611)"
  rrect20% 0.25x0.25 smd: 1(-1.875,1.25) 6(-1.875,-1.25) 7(-1.25,-1.875) 12(1.25,-1.875) 13(1.875,-1.25) 18(1.875,1.25) 19(1.25,1.875) 24(-1.25,1.875)
  rrect20% 0.35x0.25 smd: 2(-1.825,0.75) 3(-1.825,0.25) 4(-1.825,-0.25) 5(-1.825,-0.75) 14(1.825,-0.75) 15(1.825,-0.25) 16(1.825,0.25) 17(1.825,0.75)
  rrect20% 0.25x0.35 smd: 8(-0.75,-1.825) 9(-0.25,-1.825) 10(0.25,-1.825) 11(0.75,-1.825) 20(0.75,1.825) 21(0.25,1.825) 22(-0.25,1.825) 23(-0.75,1.825)
  Top Layer region: 1.9,-1.125 1.9,-1.375 1.76,-1.375 1.758,-1.375 1.753,-1.374 1.749,-1.372 1.744,-1.369 1.743,-1.368 1.743,-1.368 1.657,-1.282 1.656,-1.281 1.653,-1.276 1.651,-1.272 1.65,-1.267 1.65,-1.265 1.65,-1.265 1.65,-1.15 1.65,-1.148 1.651,-1.143 1.653,-1.138 1.656,-1.134 1.659,-1.131 1.663,-1.128 1.668,-1.126 1.673,-1.125 1.675,-1.125 1.675,-1.125
  Top Layer region: -1.9,-1.125 -1.9,-1.375 -1.76,-1.375 -1.758,-1.375 -1.753,-1.374 -1.749,-1.372 -1.744,-1.369 -1.743,-1.368 -1.743,-1.368 -1.657,-1.282 -1.656,-1.281 -1.653,-1.276 -1.651,-1.272 -1.65,-1.267 -1.65,-1.265 -1.65,-1.265 -1.65,-1.15 -1.65,-1.148 -1.651,-1.143 -1.653,-1.138 -1.656,-1.134 -1.659,-1.131 -1.663,-1.128 -1.668,-1.126 -1.673,-1.125 -1.675,-1.125 -1.675,-1.125
  Top Layer region: -1.125,-1.9 -1.375,-1.9 -1.375,-1.76 -1.375,-1.758 -1.374,-1.753 -1.372,-1.749 -1.369,-1.744 -1.368,-1.743 -1.368,-1.743 -1.282,-1.657 -1.281,-1.656 -1.276,-1.653 -1.272,-1.651 -1.267,-1.65 -1.265,-1.65 -1.265,-1.65 -1.15,-1.65 -1.148,-1.65 -1.143,-1.651 -1.138,-1.653 -1.134,-1.656 -1.131,-1.659 -1.128,-1.663 -1.126,-1.668 -1.125,-1.673 -1.125,-1.675 -1.125,-1.675
  Top Layer region: 1.125,-1.9 1.375,-1.9 1.375,-1.76 1.375,-1.758 1.374,-1.753 1.372,-1.749 1.369,-1.744 1.368,-1.743 1.368,-1.743 1.282,-1.657 1.281,-1.656 1.276,-1.653 1.272,-1.651 1.267,-1.65 1.265,-1.65 1.265,-1.65 1.15,-1.65 1.148,-1.65 1.143,-1.651 1.138,-1.653 1.134,-1.656 1.131,-1.659 1.128,-1.663 1.126,-1.668 1.125,-1.673 1.125,-1.675 1.125,-1.675
  Top Layer region: 1.9,1.125 1.9,1.375 1.76,1.375 1.758,1.375 1.753,1.374 1.749,1.372 1.744,1.369 1.743,1.368 1.743,1.368 1.657,1.282 1.656,1.281 1.653,1.276 1.651,1.272 1.65,1.267 1.65,1.265 1.65,1.265 1.65,1.15 1.65,1.148 1.651,1.143 1.653,1.138 1.656,1.134 1.659,1.131 1.663,1.128 1.668,1.126 1.673,1.125 1.675,1.125 1.675,1.125
  Top Layer region: 1.125,1.9 1.375,1.9 1.375,1.76 1.375,1.758 1.374,1.753 1.372,1.749 1.369,1.744 1.368,1.743 1.368,1.743 1.282,1.657 1.281,1.656 1.276,1.653 1.272,1.651 1.267,1.65 1.265,1.65 1.265,1.65 1.15,1.65 1.148,1.65 1.143,1.651 1.138,1.653 1.134,1.656 1.131,1.659 1.128,1.663 1.126,1.668 1.125,1.673 1.125,1.675 1.125,1.675
  Top Layer region: -1.125,1.9 -1.375,1.9 -1.375,1.76 -1.375,1.758 -1.374,1.753 -1.372,1.749 -1.369,1.744 -1.368,1.743 -1.368,1.743 -1.282,1.657 -1.281,1.656 -1.276,1.653 -1.272,1.651 -1.267,1.65 -1.265,1.65 -1.265,1.65 -1.15,1.65 -1.148,1.65 -1.143,1.651 -1.138,1.653 -1.134,1.656 -1.131,1.659 -1.128,1.663 -1.126,1.668 -1.125,1.673 -1.125,1.675 -1.125,1.675
  Top Layer region: -1.9,1.125 -1.9,1.375 -1.76,1.375 -1.758,1.375 -1.753,1.374 -1.749,1.372 -1.744,1.369 -1.743,1.368 -1.743,1.368 -1.657,1.282 -1.656,1.281 -1.653,1.276 -1.651,1.272 -1.65,1.267 -1.65,1.265 -1.65,1.265 -1.65,1.15 -1.65,1.148 -1.651,1.143 -1.653,1.138 -1.656,1.134 -1.659,1.131 -1.663,1.128 -1.668,1.126 -1.673,1.125 -1.675,1.125 -1.675,1.125
  Top Layer pour cut-out: -2.2,2.2 -2.2,-2.2 2.2,-2.2 2.2,2.2
  silkscreen extent -2,-2 2,2, body extent -2,-2 2,2, height 0.81
R0201_L [mm] "Resistor (Chip2PinSM127P600-8N)"
  rrect25% 0.34x0.32 smd: 1(-0.3,0) 2(0.3,0)
  silkscreen extent -0.29,-0.15 0.29,0.15, body extent -0.32,-0.13 0.32,0.13, height 0.3
R0402_L [mm] "Chip Resistor, 2-Leads, Body 1.0x0.5mm, IPC High Density (170210)"
  rrect20% 0.6x0.6 smd mask+0.051: 1(-0.45,0) 2(0.45,0)
  silkscreen extent -0.5,-0.25 0.5,0.25, body extent -0.5,-0.25 0.5,0.25, height 0.6
SENS_VISH_VEML6035 [mm] "(200529)"
  rrect25% 0.65x0.5 smd: 1(-0.825,0.65) 2(-0.825,0) 3(-0.825,-0.65) 4(0.825,-0.65) 5(0.825,0) 6(0.825,0.65)
  silkscreen extent -1,-1 1,1, body extent -1,-1 1,1, height 0.41
SOT23-5_L [mm] "SOT23, 5-Leads, Body 2.95x2.80mm, Pitch 0.95mm, IPC High Dens (170221)"
  rrect50% 0.9x0.6 smd: 1(-1.2,0.95) 2(-1.2,0) 3(-1.2,-0.95) 4(1.2,-0.95) 5(1.2,0.95)
  silkscreen extent -1.33,-1.55 1.3,1.55, body extent -0.87,-1.55 0.87,1.55, height 1.46
SOT563_DIODES [mm] "SOT563 (_M050_W1.2_), 6-Leads, Body 1.60x1.20, Pitch 0.5, HiDens (170926)"
  rrect25% 0.5x0.375 smd: 1(-0.85,0.5) 2(-0.85,0) 3(-0.85,-0.5) 4(0.85,-0.5) 5(0.85,0) 6(0.85,0.5)
  silkscreen extent -0.85,-0.85 0.85,0.85, body extent -0.66,-0.85 0.65,0.85, height 0.6
SOT563_L [mm] "SOT563 (_M050_W1.2_), 6-Leads, Body 1.60x1.20mm, Pitch 0.5mm, IPC High Density"
  rrect25% 0.6x0.3 smd: 1(-0.65,0.5) 2(-0.65,0) 3(-0.65,-0.5) 4(0.65,-0.5) 5(0.65,0) 6(0.65,0.5)
  silkscreen extent -0.65,-0.85 0.65,0.85, body extent -0.65,-0.85 0.65,0.85, height 0.6
SOT663_NXP [mm] "(201120)"
  rrect25% 0.55x0.55 smd paste-0.025: 1(-0.825,0.5) 2(-0.825,-0.5) 3(0.825,0)
  silkscreen extent -0.65,-0.85 0.65,0.85, body extent -0.65,-0.85 0.65,0.85, height 0.6
SW_CK_PTS810 [mm] "Switch, C&K, PTS810"
  rrect20% 1.05x0.65 smd: 1(-2.075,1.075) 2(2.075,1.075) 3(-2.075,-1.075) 4(2.075,-1.075)
  silkscreen extent -2.3,-1.6 2.3,1.6, body extent -2.1,-1.63 2.1,1.63, height 2.6
TAB50.5_T1.6_W2.4_SLIM__NOHOLES_SL [mm] "TAB50.5_T1.6_W2.4 no holes (200921)"
TDFN8_M050_2.0X3.0_EP [mm] "TDFN8_M050_2.0x3.0_EP"
  rrect25% 0.75x0.3 smd: 1(-1.5,0.75) 2(-1.5,0.25) 3(-1.5,-0.25) 4(-1.5,-0.75) 5(1.5,-0.75) 6(1.5,-0.25) 7(1.5,0.25) 8(1.5,0.75)
  rrect1% 1.36x1.46 smd paste-0.07: 9(0,0)
  silkscreen extent -1.5,-1 1.5,1, body extent -1.5,-1 1.5,1, height 1.01
TE_SMA_1814832_TH_VER [mm]
  round 2.286 hole 1.5: 1(0,0)
  round 2.54 hole 1.6: 2(-2.54,-2.54) 3(2.54,-2.54) 4(2.54,2.54) 5(-2.54,2.54)
  silkscreen extent -3.5,-3.5 3.5,3.5, body extent -3.2,-3.2 3.2,3.2, height 9.5
TESTJIGG_PCB4166_MECH2_SL [mm]
  round 1 on Mech2: 7(-14.41,-7.3) 7(-11.75,-0.35) 7(-11.596,24.385) 7(-9.6,0.67) 7(-2.2,8.35) 7(-2.2,10.95) 7(-2.15,15.65) 7(-1.26,13.28) 7(-0.05,2.55) 7(0,0) 7(0.35,16.13) 7(1.27,10.8) 7(1.27,13.32) 7(6.095,24.385) 7(6.5,0) 7(6.85,4.45) 7(7.7,8.5) 7(8.2,16.7) 7(8.6,11.45) 7(8.6,14.05) 7(8.85,6) 7(10.1,3.75)
  rect 6.7x6.7 on Mech2: 9(-6.8,7.3)
  Bottom Layer keep-out region: -2.15,16.15 -2.051,16.15 -1.867,16.074 -1.726,15.933 -1.65,15.749 -1.65,15.65 -1.65,15.65 -1.65,15.551 -1.726,15.367 -1.867,15.226 -2.051,15.15 -2.15,15.15 -2.15,15.15 -2.249,15.15 -2.433,15.226 -2.574,15.367 -2.65,15.551 -2.65,15.65 -2.65,15.749 -2.574,15.933 -2.433,16.074 -2.249,16.15 -2.15,16.15
  Bottom Layer keep-out region: -1.26,13.78 -1.161,13.78 -0.977,13.704 -0.836,13.563 -0.76,13.379 -0.76,13.28 -0.76,13.28 -0.76,13.181 -0.836,12.997 -0.977,12.856 -1.161,12.78 -1.26,12.78 -1.26,12.78 -1.359,12.78 -1.543,12.856 -1.684,12.997 -1.76,13.181 -1.76,13.28 -1.76,13.379 -1.684,13.563 -1.543,13.704 -1.359,13.78 -1.26,13.78
  Bottom Layer keep-out region: 1.27,11.3 1.369,11.3 1.553,11.224 1.694,11.083 1.77,10.899 1.77,10.8 1.77,10.8 1.77,10.701 1.694,10.517 1.553,10.376 1.369,10.3 1.27,10.3 1.27,10.3 1.171,10.3 0.987,10.376 0.846,10.517 0.77,10.701 0.77,10.8 0.77,10.899 0.846,11.083 0.987,11.224 1.171,11.3 1.27,11.3
  Bottom Layer keep-out region: 7.7,9 7.799,9 7.983,8.924 8.124,8.783 8.2,8.599 8.2,8.5 8.2,8.5 8.2,8.401 8.124,8.217 7.983,8.076 7.799,8 7.7,8 7.7,8 7.601,8 7.417,8.076 7.276,8.217 7.2,8.401 7.2,8.5 7.2,8.599 7.276,8.783 7.417,8.924 7.601,9 7.7,9
  Bottom Layer keep-out region: 10.1,4.25 10.199,4.25 10.383,4.174 10.524,4.033 10.6,3.849 10.6,3.75 10.6,3.75 10.6,3.651 10.524,3.467 10.383,3.326 10.199,3.25 10.1,3.25 10.1,3.25 10.001,3.25 9.817,3.326 9.676,3.467 9.6,3.651 9.6,3.75 9.6,3.849 9.676,4.033 9.817,4.174 10.001,4.25 10.1,4.25
  Bottom Layer keep-out region: -14.41,-6.8 -14.311,-6.8 -14.127,-6.876 -13.986,-7.017 -13.91,-7.201 -13.91,-7.3 -13.91,-7.3 -13.91,-7.399 -13.986,-7.583 -14.127,-7.724 -14.311,-7.8 -14.41,-7.8 -14.41,-7.8 -14.509,-7.8 -14.693,-7.724 -14.834,-7.583 -14.91,-7.399 -14.91,-7.3 -14.91,-7.201 -14.834,-7.017 -14.693,-6.876 -14.509,-6.8 -14.41,-6.8
TP_1.0_SMD [mm] "Test Point, 1.0 mm, SMD (170306)"
  round 1 smd paste-0.501: 1(0,0)
  silkscreen extent -0.5,-0.5 0.5,0.5
"TP_INGUN_50_OHM_CLOSED OPENVIA" [mm] "TP_INGUN_50_OHM_CLOSED"
  round 0.8 / inner round 0.7 / far side round 0.7 hole 0.4 mask+0: 1(0,0)
  round 0.5 smd paste-0.255 mask-0.41: 2(0,-1.15)
  Top Layer pour cut-out: 0,-0.8 0.105,-0.8 0.309,-0.745 0.491,-0.64 0.64,-0.491 0.745,-0.309 0.8,-0.105 0.8,0.105 0.745,0.309 0.64,0.491 0.491,0.64 0.309,0.745 0.105,0.8 0,0.8 0,0.8 -0.105,0.8 -0.309,0.745 -0.491,0.64 -0.64,0.491 -0.746,0.309 -0.8,0.105 -0.8,-0.105 -0.746,-0.309 -0.64,-0.491 -0.491,-0.64 -0.309,-0.745 -0.105,-0.8 0,-0.8
  Top Layer lines w0.7: 0,-1.15 cw(c0,0) -1.15,0 cw(c0,0) 0,-1.15
  silkscreen extent -1.5,-1.5 1.5,1.5
WCON_WF1001A-WM04E-4 [mm] "WCON, WF1001A-WM04ER1 4-terminal H: 4.87 (200622)"
  rrect25% 0.6x1.55 smd: 1(-1.5,-2.975) 2(-0.5,-2.975) 3(0.5,-2.975) 4(1.5,-2.975)
  rrect25% 1.2x1.8 smd: 5(-2.8,0) 6(2.8,0)
  silkscreen extent -3.15,-2.76 3.15,0.63, body extent -3.15,-2.2 3.15,0.7, height 4.91
WURTH_CBF_0603 [mm] "Inductor, 0603,"
  rrect25% 0.8x0.85 smd: 1(-0.7,0) 2(0.7,0)
  silkscreen extent -0.88,-0.48 0.87,0.48, body extent -0.88,-0.48 0.87,0.48, height 0.95
X_MCS_CM8V-T1A [mm] "Crystal MCS CM8V-T1A (2 pin)"
  rrect25% 0.8x1.5 smd mask+0.051: 1(-0.75,0)
  rrect25% 0.85x1.5 smd mask+0.051: 2(0.75,0)
  silkscreen extent -1,-0.6 1,0.6, body extent -1,-0.6 1,0.6, height 0.95
X_SSS_DSX211SH_2.05X1.65-4 [mm] "X_SSS_DSX211SH_2.05X1.65-4"
  rrect20% 0.9x0.8 smd mask+0.051: 1(-0.7,-0.55) 2(0.7,-0.55) 3(0.7,0.55) 4(-0.7,0.55)
  silkscreen extent -1.02,-0.82 1.02,0.82, body extent -1.07,-0.87 1.07,0.87, height 0.51
ZGM230S [mm] "no datasheet"
  rect 0.35x0.25 smd paste-0.03 mask+0.04: 1(-2.9,2.5) 2(-2.9,2) 3(-2.9,1.5) 4(-2.9,1) 5(-2.9,0.5) 6(-2.9,0) 7(-2.9,-0.5) 8(-2.9,-1) 9(-2.9,-1.5) 10(-2.9,-2) 11(-2.9,-2.5) 23(2.9,-2.5) 24(2.9,-2) 25(2.9,-1.5) 26(2.9,-1) 27(2.9,-0.5) 28(2.9,0) 29(2.9,0.5) 30(2.9,1) 31(2.9,1.5) 32(2.9,2) 33(2.9,2.5)
  rect 0.25x0.35 smd paste-0.03 mask+0.04: 12(-2.5,-2.9) 13(-2,-2.9) 14(-1.5,-2.9) 15(-1,-2.9) 16(-0.5,-2.9) 17(0,-2.9) 18(0.5,-2.9) 19(1,-2.9) 20(1.5,-2.9) 21(2,-2.9) 22(2.5,-2.9) 34(2.5,2.9) 35(2,2.9) 36(1.5,2.9) 37(1,2.9) 38(0.5,2.9) 39(0,2.9) 40(-0.5,2.9) 41(-1,2.9) 42(-1.5,2.9) 43(-2,2.9) 44(-2.5,2.9)
  rect 0.5x0.5 smd paste-0.03 mask+0.04: 45(-0.45,0.45) 46(-0.45,-0.45) 47(0.45,-0.45) 48(0.45,0.45)
  silkscreen extent -3.85,-3.25 3.25,3.25, body extent -3.25,-3.25 3.25,3.25, height 1.3

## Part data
LED900: library part Blue

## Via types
v1: diameter 0.5, hole 0.25, Top Layer to Bottom Layer, tented both sides, 645 vias

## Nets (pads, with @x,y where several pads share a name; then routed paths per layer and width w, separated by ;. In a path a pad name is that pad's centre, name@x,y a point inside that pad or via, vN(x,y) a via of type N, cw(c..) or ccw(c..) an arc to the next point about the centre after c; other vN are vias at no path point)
3V3: C917.1 EXP1.20 Q901.1 Q902.4 R908.2 R918.2 U902.1 U902.4 | length 71
  Signal Layer 5 w0.635: v1(8.629,36.818) 9.554,37.744 9.554,39.787 v1(9.541,39.801) ; v1(11.971,39.62) v1(12.64,39.62) 12.751,39.509 12.751,35.788 13.785,34.754 17.779,34.754 19.542,36.516 19.542,37.989 20.795,39.242 22.75,39.242 23.236,39.728 24.517,39.728 25.479,40.69 28.982,40.69 29.595,40.077 29.595,38.362 30.971,36.986 30.971,11.725 32.056,10.64 EXP1.20@34.261,10.64
  Signal Layer 3 w0.635: v1(9.541,39.801) 9.722,39.62 v1(12.64,39.62)
  Bottom Layer w0.1: R908.2@9.465,41.91 R908.2@9.465,41.92
  Bottom Layer w0.2: R908.2@9.465,41.91 9.465,40.695 9.94,40.22 10.165,40.22
  Bottom Layer w0.3: v1(8.629,36.818) 8.668,36.857 8.668,37.137 8.966,37.435 9.18,37.435 R918.2@9.19,37.445 ; U902.4@10.26,40.22 U902.4@10.365,40.22
  Bottom Layer w0.381: v1@11.865,39.846 U902.1@11.865,40.22
  Bottom Layer w0.4: Q901.1@12.99,34.983 13.557,34.983 v1(13.566,34.973)
  Bottom Layer w0.508: v1(9.541,39.801) 9.841,39.801 U902.4@10.26,40.22
  Bottom Layer w0.635: v1(8.629,36.818) 8.853,36.595 9.028,36.595 ; v1(12.64,39.62) 12.64,39.695 C917.1@13.165,40.22
5V: C915.1 C916.1 D901.1 EXP1.18 Q901.2 Q901.5 R907.2 R915.2 U902.2 | length 62.5
  Signal Layer 5 w0.5: v1(11.382,17.332) 11.382,20.573 10.338,21.618 10.338,23.629 9.699,24.267 9.699,26.805 12.476,29.583 12.476,32.824 v1(11.485,33.816) 11.972,34.303 v1(11.972,38.77) v1@11.857,38.885
  Signal Layer 5 w0.635: v1@11.857,38.885 11.453,38.885 10.972,39.366 10.972,41.946 11.561,42.535 12.296,42.535 v1(12.34,42.491)
  Signal Layer 3 w0.635: v1(11.382,17.332) 11.43,17.284 11.43,16.865 13.133,15.163 30.965,15.163 32.763,13.365 34.076,13.365 EXP1.18@34.261,13.18
  Bottom Layer w0.1: Q901.2@12.34,34.983 Q901.5@12.34,36.808
  Bottom Layer w0.25: R907.2@12.19,43.27 12.2,43.27 12.34,43.13 v1(12.34,42.491)
  Bottom Layer w0.3: v1(11.485,33.816) 12.019,34.35 12.33,34.35 12.34,34.36 R915.2@12.34,34.37 Q901.2@12.34,34.983
  Bottom Layer w0.381: C915.1@11.086,38.716 11.365,38.995 C916.1@11.365,39.47 ; C916.1@11.358,39.47 11.358,40.213 U902.2@11.365,40.22
  Bottom Layer w0.635: C915.1@11.165,38.77 v1(11.972,38.77) ; v1(11.382,17.332) 11.382,18.802 D901.1@11.43,18.85
50R_P1: P1.1 TP1.1 U1.3 | length 16.9
  Top Layer w0.25: U1.3@20.915,44.6 21.488,44.6
  Top Layer w0.457: 21.488,44.6 22.66,44.6 TP1.1@24.625,42.635 26.875,42.635 30.48,46.24 P1.1@30.48,51.3
BOARD_ID_SCL: EXP1.17 R911.1 TPJ14.1 U900.H13 U903.6 | length 61.5
  Signal Layer 2 w0.102: v1(28.48,29.7) 27.662,28.882 27.662,17.299 29.262,15.699 v1(29.262,14.361)
  Signal Layer 3 w0.1: EXP1.17@1.3,13.18 2.645,13.18 3.623,14.158 v1(8.713,14.158) 9.158,13.714 19.13,13.714 20.111,14.695 28.928,14.695 v1(29.262,14.361)
  Bottom Layer w0.102: v1(8.713,14.158) 8.723,14.168 8.723,14.501 9.929,15.707 11.138,15.707 13.279,17.849 13.279,21.551 U900.H13@12.33,22.5 ; U903.6@24.155,29.975 R911.1@25.055,29.975 ; R911.1@25.055,30 R911.1@25.08,29.975 25.405,30.3 26.53,30.3 TPJ14.1@27.13,29.7 v1(28.48,29.7)
BOARD_ID_SDA: EXP1.19 R910.1 TPJ15.1 U900.G13 U900.H12 U900.J12 U903.5 | length 72.2
  Signal Layer 2 w0.1: v1(21.904,31.066) 21.52,30.682 21.52,29.812 22.205,29.127 22.205,27.526 21.995,27.316 21.995,22.224 21.625,21.854 21.625,18.089 23.497,16.217 25.752,16.217 v1(28.713,13.256)
  Signal Layer 3 w0.1: EXP1.19@1.3,10.64 1.506,10.64 4.212,13.346 8.057,13.346 v1(8.108,13.398) 8.175,13.331 8.508,13.331 8.558,13.281 8.569,13.291 19.384,13.291 20.345,14.253 27.775,14.253 28.713,13.315 v1(28.713,13.256)
  Bottom Layer w0.1: v1(8.108,13.398) 8.108,14.187 9.86,15.938 11.081,15.938 13.078,17.936 13.078,21.468 12.294,22.252 12.078,22.252 U900.G13@11.83,22.5 U900.H12@12.33,23 U900.J12@12.83,23 ; v1(21.904,31.066) 22.32,30.65 23.48,30.65 23.655,30.475 U903.5@24.155,30.475 24.23,30.55 25.005,30.55 R910.1@25.08,30.625 25.995,31.54 26.37,31.54 TPJ15.1@27.13,32.3
BOARD_ID_WP: R912.1 TPJ16.1 U900.F13 U903.7 | length 28.5
  Signal Layer 3 w0.1: v1(11.58,22.1) 11.652,22.1 11.952,22.4 14.586,22.4 14.936,22.05
  Signal Layer 3 w0.102: 14.936,22.05 15.893,22.05 16.255,22.413 16.587,22.413 16.95,22.051 16.95,21.364 17.353,20.961 20.132,20.961 22.018,19.075 v1(23.055,19.075)
  Bottom Layer w0.102: U900.F13@11.33,22.5 11.58,22.25 v1(11.58,22.1) ; TPJ16.1@25.03,18.25 23.88,18.25 v1(23.055,19.075) 23.53,19.55 23.53,29.125 23.88,29.475 U903.7@24.155,29.475 25.005,29.475 R912.1@25.08,29.4
BUTTON0: C142.1 EXP1.3 R140.2 SW100.1 SW100.2 U1.8 U900.A6 | length 115.5
  Top Layer w0.1: U1.8@20.785,47.1 21.472,47.1 v1(22.407,48.035) ; R140.2@23.2,1.304 23.579,1.304 23.594,1.319 C142.1@23.85,1.319 24.832,1.319 SW100.2@24.968,1.183 ; SW100.2@24.91,1.125 SW100.2@24.968,1.183 ; v1(28.833,13.87) 29.421,13.87 30.67,12.621 30.67,1.775 30.02,1.125 SW100.1@29.06,1.125 28.894,1.291 25.076,1.291 SW100.2@24.968,1.183
  Signal Layer 2 w0.1: v1(3.155,13.088) 3.822,13.755 v1(3.822,25.441) 3.822,26.23 3.822,30.564 v1(4.235,30.977) 7.487,34.229 7.487,40.727 8.941,42.181 8.941,50.52 11.176,52.756 19.675,52.756 22.332,50.099 22.332,48.11 v1(22.407,48.035)
  Signal Layer 3 w0.1: EXP1.3@1.3,30.96 2.918,30.96 2.935,30.977 v1(4.235,30.977) ; v1(3.155,13.088) 3.671,13.088 4.391,13.808 8.498,13.808 8.792,13.514 19.323,13.514 20.304,14.495 28.207,14.495 v1(28.833,13.87)
  Bottom Layer w0.1: v1(3.822,25.441) 6.329,25.441 6.562,25.675 7.896,25.675 8.221,26 U900.A6@8.83,26
BUTTON1: C145.1 EXP1.5 R143.2 SW101.1 SW101.2 U1.9 U900.A5 | length 83.8
  Top Layer w0.1: v1(4.846,3.451) 4.954,3.451 5.141,3.264 6.499,3.264 SW101.1@6.51,3.275 SW101.2@10.66,3.275 10.73,3.205 C145.1@11.72,3.205 11.733,3.218 12.313,3.218 R143.2@12.325,3.23 ; U1.9@20.785,47.6 20.805,47.62 21.24,47.62 v1(21.26,47.641)
  Signal Layer 2 w0.1: v1(4.846,3.451) 4.222,4.075 v1(4.222,26.669) 4.222,30.314 7.687,33.779 7.687,40.575 9.141,42.029 9.141,50.425 11.258,52.542 19.606,52.542 22.092,50.056 22.092,48.473 v1(21.26,47.641)
  Signal Layer 3 w0.1: EXP1.5@1.3,28.42 2.471,28.42 v1(4.222,26.669)
  Bottom Layer w0.1: v1(4.222,26.669) 5.041,25.85 6.455,25.85 6.58,25.975 7.878,25.975 8.403,26.5 U900.A5@8.83,26.5
CTRL_MCU_PA0: R919.1 U900.C2 U900.D3 | length 2.7
  Bottom Layer w0.1: R919.1@8.98,29.6 9.58,29 9.58,28.25 U900.C2@9.83,28 U900.D3@10.33,27.5
CTRL_MCU_PA1: R920.1 U900.C1 | length 1.1
  Bottom Layer w0.1: U900.C1@9.83,28.5 R920.1@9.83,29.575
CTRL_MCU_PB9: TPJ17.1 U900.L8 U900.M7 | length 6.1
  Signal Layer 3 w0.1: v1(12.73,25) 14.215,25 v1(15.437,26.221)
  Bottom Layer w0.1: v1(12.73,25) U900.L8@13.83,25 U900.M7@14.33,25.5 ; v1(15.437,26.221) 15.837,26.221 16.215,26.6 TPJ17.1@16.33,26.6
CTRL_MCU_PB10: R905.1 U900.L9 | length 28.1
  Top Layer w0.2: v1(19.706,17.879) 19.787,17.879 20.002,17.664 21.649,17.664 25.094,14.218 25.094,12.11 27.516,9.688 27.516,8.934 R905.1@27.9,8.55
  Signal Layer 2 w0.2: v1(12.28,24.55) 12.934,24.55 13.161,24.776 14.374,24.776 14.719,24.431 16.884,24.431 18.39,22.925 18.39,21.29 19.1,20.58 19.1,18.415 19.636,17.879 v1(19.706,17.879)
  Bottom Layer w0.1: v1(12.28,24.55) 12.33,24.5 12.905,24.5 13.138,24.733 13.597,24.733 U900.L9@13.83,24.5
CTRL_MCU_PB13: U900.N9 X900.3 | length 3.2
  Bottom Layer w0.1: U900.N9@14.83,24.5 16.005,24.5 16.18,24.675 17.105,24.675 X900.3@17.73,25.3
CTRL_MCU_PB14: U900.N10 X900.1 | length 2.1
  Bottom Layer w0.1: U900.N10@14.83,24 15.1,24.27 16.282,24.27 16.63,23.922 X900.1@16.63,23.9
CTRL_MCU_PC2: R921.1 U900.L1 | length 0.9
  Bottom Layer w0.1: U900.L1@13.83,28.5 R921.1@13.83,29.427
CTRL_MCU_PD0: C923.1 R901.1 U900.L10 | length 6
  Top Layer w0.1: v1@13.322,24.326 v1@13.329,24.326
  Signal Layer 2 w0.1: v1(13.347,24.326) 14.349,23.324 14.349,21.717 v1(15.224,20.842)
  Bottom Layer w0.1: v1@13.322,24.326 13.322,24.308 13.63,24 U900.L10@13.83,24 ; C923.1@14.175,20.825 14.188,20.838 14.788,20.838 R901.1@14.8,20.85 ; R901.1@14.8,20.846 15.22,20.846 v1(15.224,20.842)
CTRL_MCU_PE0: TPJ11.1 U900.G11 | length 21.3
  Signal Layer 3 w0.1: v1(11.605,24.526) 11.605,23.909 11.989,23.525 14.247,23.525 14.737,24.015 24.556,24.015 25.004,23.566 v1(28.857,23.566)
  Bottom Layer w0.1: v1(11.605,24.526) 11.605,23.725 U900.G11@11.83,23.5 U900.G11@11.786,23.5 ; TPJ11.1@27.38,24.25 28.173,24.25 v1(28.857,23.566)
CTRL_MCU_PE4: R931.1 U900.C11 | length 12.7
  Signal Layer 5 w0.1: v1(12.105,25.201) 12.631,25.727 13.693,25.727 14.397,26.43 14.397,28.114 15.067,28.785 16.555,28.785 16.651,28.689 v1(18.263,28.689)
  Bottom Layer w0.1: U900.C11@9.83,23.5 10.135,23.805 10.31,23.805 11.48,24.975 11.879,24.975 v1(12.105,25.201)
  Bottom Layer w0.3: v1(18.263,28.689) 18.301,28.65 18.52,28.65 19.07,28.1 R931.1@19.08,28.1
CTRL_MCU_PE14: TPJ5.1 U900.A2 | length 11.6
  Signal Layer 3 w0.1: v1(8.24,28.081) 9.028,28.87 12.09,28.87 14.225,31.005 15.98,31.005 16.182,30.803 v1(16.29,30.803)
  Bottom Layer w0.1: v1(8.24,28.081) 8.321,28 U900.A2@8.83,28 ; v1(16.29,30.803) 16.29,29.24 TPJ5.1@16.33,29.2
CTRL_MCU_PE15: TPJ6.1 U900.A1 | length 13.7
  Signal Layer 3 w0.1: v1(8.24,28.725) 8.6,29.085 12.007,29.085 14.169,31.248 18.469,31.248 18.696,31.021 v1(19.275,31.021)
  Bottom Layer w0.1: v1@8.13,28.725 v1(8.24,28.725) 8.605,28.725 U900.A1@8.83,28.5
  Bottom Layer w0.102: v1(19.275,31.021) 19.275,31.033 19.8,31.558 TPJ6.1@19.8,31.57
CTRL_MCU_PF0: TPJ2.1 U900.C10 | length 16.4
  Signal Layer 5 w0.1: v1(11.475,25.381) 12.663,26.57 13.63,26.57 14.129,27.068 14.129,28.188 14.995,29.054 16.247,29.054 17.703,30.51 17.703,33.08 18.36,33.738 v1(19.189,33.738)
  Bottom Layer w0.1: U900.C10@9.83,24 10.047,24 10.052,24.005 10.21,24.005 11.475,25.27 v1(11.475,25.381) ; TPJ2.1@18.88,34.38 19.052,34.208 19.052,33.819 19.133,33.738 v1(19.189,33.738)
CTRL_MCU_PF1: TPJ1.1 U900.A9 U900.B10 | length 19.4
  Signal Layer 2 w0.1: v1(8.38,24.526) 8.405,24.526 9.085,23.846 9.085,17.585 8.877,17.377 v1(8.877,17.295)
  Signal Layer 3 w0.1: v1(8.877,17.295) 8.893,17.295 9.798,18.2 12.549,18.2 13.018,17.731 15.376,17.731 15.609,17.499 16.516,17.499 16.922,17.905 v1(17.739,17.905)
  Bottom Layer w0.1: v1(8.38,24.526) 8.393,24.513 8.805,24.513 8.811,24.519 U900.B10@9.33,24 ; v1(17.739,17.905) 17.815,17.982 18.018,17.982 18.286,18.25 TPJ1.1@18.53,18.25
CTRL_MCU_PF2: TPJ3.1 U900.A10 | length 16.7
  Signal Layer 2 w0.1: v1(7.995,19.591) 8.845,20.441 8.845,23.416 8.428,23.833 v1(8.428,23.898)
  Signal Layer 3 w0.1: v1(7.995,19.591) 8.343,19.243 11.639,19.243 12.402,20.006 17.153,20.006 17.36,20.213 v1(18.085,20.213)
  Bottom Layer w0.1: v1(8.428,23.898) 8.537,23.898 8.619,23.981 8.811,23.981 U900.A10@8.83,24 ; v1(18.085,20.213) 18.085,20.309 18.478,20.702 18.48,20.702 TPJ3.1@18.48,20.8
CTRL_MCU_PF5: TP999.1 U900.A8 | length 27.9
  Signal Layer 2 w0.1: TP999.1@2.4,2.4 4.903,2.4 5.552,3.049 5.552,13.254 9.285,16.987 9.285,24.221 v1@8.38,25.126
  Bottom Layer w0.1: v1@8.38,25.126 8.397,25.109 8.721,25.109 U900.A8@8.83,25
  other v1: 8.38,25.17
CTRL_MCU_PF7: R932.1 U900.A7 | length 1.7
  Bottom Layer w0.1: R932.1@7.408,25.15 7.678,25.15 8.138,25.61 8.693,25.61 8.803,25.5 U900.A7@8.83,25.5
CTRL_MCU_PF10: R903.2 U900.B13 | length 1.5
  Bottom Layer w0.2: U900.B13@9.33,22.5 9.21,22.38 9.21,21.32 R903.2@9.38,21.15
CTRL_MCU_PF11: R904.2 U900.A13 | length 1.5
  Bottom Layer w0.2: R904.2@8.505,21.15 8.905,21.55 8.905,22.425 U900.A13@8.83,22.5
DBG_3V3: C914.1 C919.1 Q902.3 R906.2 R910.2 R911.2 R912.2 R929.2 R933.1 U901.A1 U901.E3 U903.8 | length 43.3
  Signal Layer 5 w0.4: v1(5.957,26.777) 5.958,26.776 6.841,26.776 7.561,27.496 7.561,28.082 v1(7.58,28.101) 7.58,30.149 7.066,30.663 7.066,33.292 v1(8.495,34.721)
  Signal Layer 3 w0.4: v1(8.495,34.721) v1@8.495,34.743
  Signal Layer 3 w0.508: v1(7.58,28.101) 7.58,27.725 7.833,27.472 8.677,27.472 9.607,28.402 12.275,28.402 14.474,30.601 15.552,30.601 16.003,30.15 18.47,30.15 19.233,29.386 20.188,29.386 20.201,29.399 22.761,29.399 22.774,29.386 25.334,29.386 ; v1(25.571,28.326) 25.4,28.498 25.4,29.32 25.334,29.386 ; v1(26.118,30.758) 26.118,30.038 25.466,29.386 25.334,29.386
  Bottom Layer w0.2: Q902.3@9.215,35.32 9.215,35.655 9.517,35.957 10.377,35.957 R929.2@10.915,36.495 R933.1@10.915,37.095 ; C919.1@25.255,28.85 25.255,28.925 25.68,29.35 R912.2@25.68,29.4
  Bottom Layer w0.203: v1(5.957,26.777) 6.008,26.777 6.128,26.657 6.128,26.654 6.834,26.654 U901.E3@6.98,26.8 ; C914.1@7.505,28.6 7.543,28.562 7.543,28.139 v1(7.58,28.101) ; C914.1@7.525,28.625 7.53,28.63 R906.2@7.53,29.2 ; v1@7.605,28.126 7.68,28.052 U901.A1@7.68,27.6
  Bottom Layer w0.25: Q902.3@9.19,35.295 Q902.3@9.215,35.32
  Bottom Layer w0.3: v1(8.495,34.721) 8.511,34.737 8.511,35.052 8.755,35.295 Q902.3@9.19,35.295 ; U903.8@24.155,28.975 24.555,28.975 24.68,28.85 C919.1@25.105,28.85 ; C919.1@25.255,28.825 25.275,28.825 25.285,28.815 25.285,28.667 25.571,28.381 v1(25.571,28.326) ; R912.2@25.68,29.4 R911.2@25.68,29.95 ; R910.2@25.68,30.625 25.69,30.635 25.942,30.635 26.064,30.758 v1(26.118,30.758)
DBG_SPI_CS: R906.1 U900.B1 U900.B2 U901.A3 | length 5.7
  Bottom Layer w0.1: R906.1@6.93,29.1 6.94,29.1 7.049,29.209 R906.1@7.049,29.219 ; U901.A3@6.98,27.6 6.98,27.605 6.866,27.719 6.787,27.719 6.549,27.957 6.549,28.829 6.92,29.2 6.94,29.2 7.05,29.31 7.05,29.32 7.365,29.635 8.195,29.635 U900.B1@9.33,28.5 U900.B2@9.33,28
DBG_SPI_MISO: U900.A4 U900.B3 U901.C3 | length 7.5
  Bottom Layer w0.1: U901.C3@6.98,27.2 5.788,27.2 5.535,26.946 5.535,26.354 5.664,26.225 7.805,26.225 8.58,27 U900.A4@8.83,27 9.08,26.75 9.505,26.75 9.58,26.825 9.58,27.25 U900.B3@9.33,27.5
DBG_SPI_MOSI: U900.C3 U901.D2 | length 3.6
  Bottom Layer w0.1: U901.D2@7.33,27 7.33,26.7 7.505,26.525 7.805,26.525 8.53,27.25 8.98,27.25 9.08,27.35 9.08,27.625 9.205,27.75 9.58,27.75 U900.C3@9.83,27.5
DBG_SPI_SCLK: U900.A3 U901.E1 | length 1.4
  Bottom Layer w0.1: U901.E1@7.68,26.8 8.38,27.5 U900.A3@8.83,27.5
